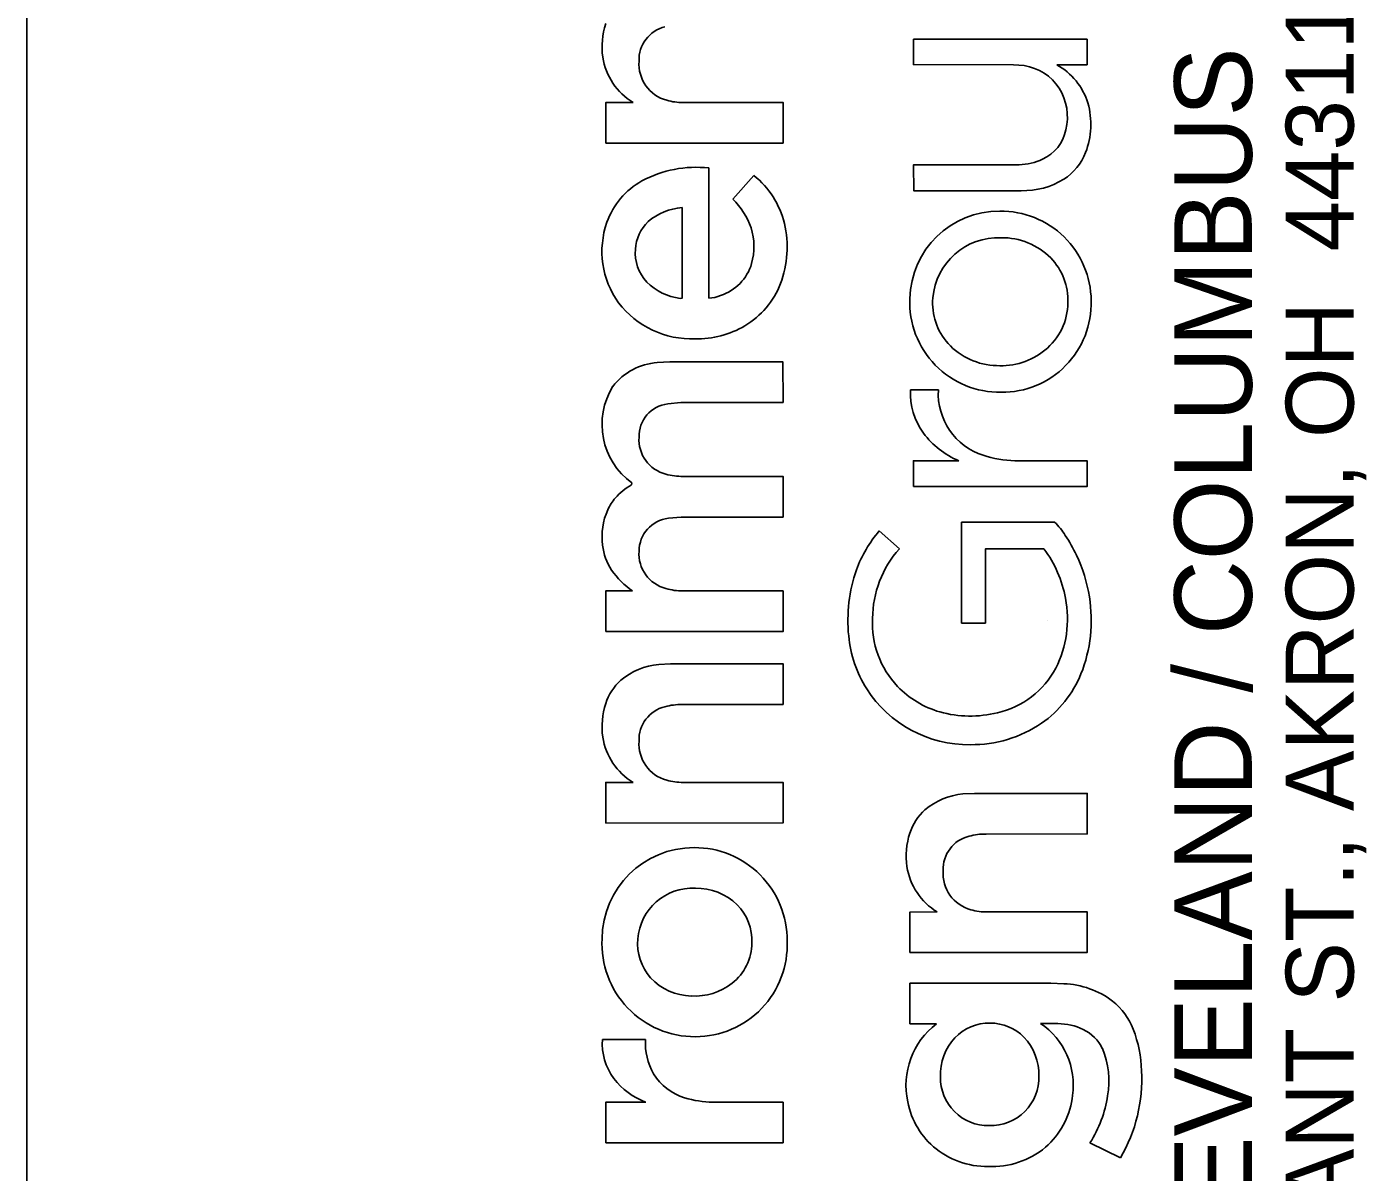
# Model space of a CAD drawing. Extents: x -7 to 3400, y -220 to 22.
# Drawn here: x 32 to 32.984, y 3.594 to 4.436 of the extents above; entities that cross this region are included whole.
import ezdxf

# ---------------------------------------------------------------- set-up
doc = ezdxf.new("R2010")
doc.units = 0
doc.layers.add('SH_Border', color=7, linetype='Continuous')
doc.layers.add('SH_Data', color=7, linetype='Continuous')

msp = doc.modelspace()

# ---------------------------------------------------------------- linework, layer by layer
at = {"layer": 'SH_Border'}
msp.add_line((32, 0.5), (32, 21.5), dxfattribs=at)
at = {"layer": 'SH_Data'}
for p, q in [((32.65152, 4.40801), (32.65153, 4.42672)), ((32.65153, 4.42672), (32.7791, 4.42664)), ((32.7791, 4.42664), (32.77908, 4.40796)), ((32.7249, 4.40796), (32.65152, 4.40801)), ((32.7328, 4.40727), (32.7249, 4.40796)), ((32.77908, 4.40796), (32.75689, 4.40796)), ((32.42542, 4.38016), (32.44552, 4.38021)), ((32.42542, 4.35035), (32.42542, 4.38016)), ((32.48222, 4.38021), (32.55569, 4.38021)), ((32.55569, 4.38021), (32.55571, 4.35045)), ((32.55571, 4.35045), (32.42542, 4.35035)), ((32.50108, 4.33209), (32.50118, 4.23657)), ((32.65154, 4.33443), (32.72905, 4.3345)), ((32.65165, 4.31543), (32.65154, 4.33443)), ((32.51882, 4.30927), (32.53422, 4.32662)), ((32.73073, 4.31543), (32.65165, 4.31543)), ((32.48144, 4.23644), (32.48144, 4.30296)), ((32.48016, 4.23628), (32.48144, 4.23644)), ((32.46329, 4.18915), (32.47259, 4.18968)), ((32.47259, 4.18968), (32.55557, 4.18968)), ((32.55557, 4.18968), (32.55571, 4.15982)), ((32.64932, 4.16907), (32.66978, 4.16907)), ((32.48058, 4.15981), (32.47102, 4.15881)), ((32.55571, 4.15982), (32.48058, 4.15981)), ((32.65152, 4.11699), (32.68476, 4.117)), ((32.65152, 4.098), (32.65152, 4.11699)), ((32.72605, 4.11703), (32.7791, 4.11696)), ((32.7791, 4.11696), (32.77903, 4.098)), ((32.48218, 4.10553), (32.55571, 4.10548)), ((32.55571, 4.10548), (32.55571, 4.07568)), ((32.44443, 4.09922), (32.44455, 4.10072)), ((32.77903, 4.098), (32.65152, 4.098)), ((32.4809, 4.07567), (32.47143, 4.07474)), ((32.55571, 4.07568), (32.4809, 4.07567)), ((32.62636, 4.06548), (32.64114, 4.05241)), ((32.6868, 4.07185), (32.75516, 4.07192)), ((32.6868, 3.99778), (32.6868, 4.07185)), ((32.70448, 4.05241), (32.70432, 3.99775)), ((32.74737, 4.05227), (32.70448, 4.05241)), ((32.42542, 3.99152), (32.42545, 4.02138)), ((32.42545, 4.02138), (32.44515, 4.02138)), ((32.48206, 4.02138), (32.55571, 4.02136)), ((32.55571, 4.02136), (32.55571, 3.99156)), ((32.70432, 3.99775), (32.6868, 3.99778)), ((32.75, 4), (32.75, 4)), ((32.55571, 3.99156), (32.42542, 3.99152)), ((32.46439, 3.96736), (32.47289, 3.96783)), ((32.47289, 3.96783), (32.55571, 3.96783)), ((32.55571, 3.96783), (32.55571, 3.93804)), ((32.55571, 3.93804), (32.4814, 3.93796)), ((32.42542, 3.88066), (32.44552, 3.88071)), ((32.42542, 3.85086), (32.42542, 3.88066)), ((32.48222, 3.88071), (32.55569, 3.88071)), ((32.55569, 3.88071), (32.55571, 3.85096)), ((32.68784, 3.8722), (32.69634, 3.87266)), ((32.69634, 3.87266), (32.77916, 3.87266)), ((32.77916, 3.87266), (32.77917, 3.84287)), ((32.55571, 3.85096), (32.42542, 3.85086)), ((32.77917, 3.84287), (32.70485, 3.8428)), ((32.64888, 3.7855), (32.66897, 3.78555)), ((32.64888, 3.75569), (32.64888, 3.7855)), ((32.70568, 3.78555), (32.77915, 3.78555)), ((32.77915, 3.78555), (32.77917, 3.75579)), ((32.77917, 3.75579), (32.64888, 3.75569)), ((32.6489, 3.70336), (32.64889, 3.73322)), ((32.64889, 3.73322), (32.75236, 3.73322)), ((32.75236, 3.73322), (32.76191, 3.73285)), ((32.66836, 3.70336), (32.6489, 3.70336)), ((32.75763, 3.70356), (32.74487, 3.70361)), ((32.42299, 3.69193), (32.45454, 3.69193)), ((32.42542, 3.64577), (32.45473, 3.64579)), ((32.42542, 3.61593), (32.42542, 3.64577)), ((32.50413, 3.64581), (32.55571, 3.64573)), ((32.55571, 3.64573), (32.55565, 3.61593)), ((32.55565, 3.61593), (32.42542, 3.61593)), ((32.8036, 3.60491), (32.7812, 3.61598))]:
    msp.add_line(p, q, dxfattribs=at)
for points in [[(32.7328, 4.40727), (32.7249, 4.40796), (32.65152, 4.40801), (32.65153, 4.42672), (32.7791, 4.42664), (32.77908, 4.40796), (32.75689, 4.40796)], [(32.42542, 4.35035), (32.42542, 4.38016), (32.44552, 4.38021)], [(32.48222, 4.38021), (32.55569, 4.38021), (32.55571, 4.35045), (32.42542, 4.35035)], [(32.50108, 4.33209), (32.50118, 4.23657)], [(32.73073, 4.31543), (32.65165, 4.31543), (32.65154, 4.33443), (32.72905, 4.3345)], [(32.51882, 4.30927), (32.53422, 4.32662)], [(32.48016, 4.23628), (32.48144, 4.23644), (32.48144, 4.30296)], [(32.46329, 4.18915), (32.47259, 4.18968), (32.55557, 4.18968), (32.55571, 4.15982), (32.48058, 4.15981), (32.47102, 4.15881)], [(32.64932, 4.16907), (32.66978, 4.16907)], [(32.72605, 4.11703), (32.7791, 4.11696), (32.77903, 4.098), (32.65152, 4.098)], [(32.65152, 4.098), (32.65152, 4.11699), (32.68476, 4.117)], [(32.48218, 4.10553), (32.55571, 4.10548), (32.55571, 4.07568), (32.4809, 4.07567), (32.47143, 4.07474)], [(32.44443, 4.09922), (32.44455, 4.10072)], [(32.62636, 4.06548), (32.64114, 4.05241)], [(32.74737, 4.05227), (32.70448, 4.05241), (32.70432, 3.99775), (32.6868, 3.99778), (32.6868, 4.07185), (32.75516, 4.07192)], [(32.42542, 3.99152), (32.42545, 4.02138), (32.44515, 4.02138)], [(32.48206, 4.02138), (32.55571, 4.02136), (32.55571, 3.99156), (32.42542, 3.99152)], [(32.46439, 3.96736), (32.47289, 3.96783), (32.55571, 3.96783), (32.55571, 3.93804), (32.4814, 3.93796)], [(32.42542, 3.85086), (32.42542, 3.88066), (32.44552, 3.88071)], [(32.48222, 3.88071), (32.55569, 3.88071), (32.55571, 3.85096), (32.42542, 3.85086)], [(32.68784, 3.8722), (32.69634, 3.87266), (32.77916, 3.87266), (32.77917, 3.84287), (32.70485, 3.8428)], [(32.64888, 3.75569), (32.64888, 3.7855), (32.66897, 3.78555)], [(32.70568, 3.78555), (32.77915, 3.78555), (32.77917, 3.75579), (32.64888, 3.75569)], [(32.66836, 3.70336), (32.6489, 3.70336), (32.64889, 3.73322), (32.75236, 3.73322), (32.76191, 3.73285)], [(32.75763, 3.70356), (32.74487, 3.70361)], [(32.42299, 3.69193), (32.45454, 3.69193)], [(32.50413, 3.64581), (32.55571, 3.64573), (32.55565, 3.61593), (32.42542, 3.61593)], [(32.42542, 3.61593), (32.42542, 3.64577), (32.45473, 3.64579)], [(32.8036, 3.60491), (32.7812, 3.61598)]]:
    msp.add_lwpolyline(points, dxfattribs=at)
for centre, radius, start, end in [((32.47872, 4.42108), 0.05602, 162.27398, 187.79173), ((32.47872, 4.42108), 0.05602, 162.27398, 187.79173), ((32.47482, 4.41155), 0.02498, 103.68683, 182.21395), ((32.47482, 4.41155), 0.02498, 103.68683, 182.21395), ((32.47027, 4.4209), 0.04763, 188.96462, 238.69865), ((32.47027, 4.4209), 0.04763, 188.96462, 238.69865), ((32.47735, 4.40846), 0.02757, 175.58441, 255.13816), ((32.47735, 4.40846), 0.02757, 175.58441, 255.13816), ((32.72711, 4.36998), 0.03772, 33.50082, 81.32954), ((32.72711, 4.36998), 0.03772, 33.50082, 81.32954), ((32.73239, 4.36485), 0.04959, 17.62209, 60.38974), ((32.73239, 4.36485), 0.04959, 17.62209, 60.38974), ((32.72414, 4.3695), 0.04048, 346.56179, 31.75389), ((32.72414, 4.3695), 0.04048, 346.56179, 31.75389), ((32.48183, 4.42235), 0.04215, 254.08913, 270.52838), ((32.48183, 4.42235), 0.04215, 254.08913, 270.52838), ((32.72343, 4.36415), 0.05838, 339.16197, 15.61485), ((32.72343, 4.36415), 0.05838, 339.16197, 15.61485), ((32.73371, 4.36616), 0.03042, 294.63214, 348.48625), ((32.73371, 4.36616), 0.03042, 294.63214, 348.48625), ((32.739, 4.35901), 0.04201, 303.10391, 338.15613), ((32.739, 4.35901), 0.04201, 303.10391, 338.15613), ((32.49176, 4.24874), 0.08387, 83.62118, 118.28448), ((32.49176, 4.24874), 0.08387, 83.62118, 118.28448), ((32.72747, 4.38081), 0.04633, 271.95199, 294.08943), ((32.72747, 4.38081), 0.04633, 271.95199, 294.08943), ((32.47894, 4.27368), 0.05583, 118.82935, 160.62242), ((32.47894, 4.27368), 0.05583, 118.82935, 160.62242), ((32.49399, 4.2763), 0.06443, 13.53275, 51.36266), ((32.49399, 4.2763), 0.06443, 13.53275, 51.36266), ((32.7321, 4.37256), 0.05715, 268.62699, 301.47779), ((32.7321, 4.37256), 0.05715, 268.62699, 301.47779), ((32.4844, 4.26071), 0.04236, 94.01311, 130.88062), ((32.4844, 4.26071), 0.04236, 94.01311, 130.88062), ((32.48033, 4.27018), 0.05485, 19.0387, 45.44322), ((32.48033, 4.27018), 0.05485, 19.0387, 45.44322), ((32.48697, 4.27074), 0.06438, 160.52138, 215.78155), ((32.48697, 4.27074), 0.06438, 160.52138, 215.78155), ((32.47703, 4.2709), 0.02985, 132.98553, 177.1802), ((32.47703, 4.2709), 0.02985, 132.98553, 177.1802), ((32.48289, 4.27384), 0.0758, 339.35431, 13.37708), ((32.48289, 4.27384), 0.0758, 339.35431, 13.37708), ((32.71435, 4.23484), 0.06552, 89.48213, 178.77752), ((32.71435, 4.23484), 0.06552, 89.48213, 178.77752), ((32.71582, 4.23414), 0.06623, 0.42265, 90.7613), ((32.71582, 4.23414), 0.06623, 0.42265, 90.7613), ((32.48724, 4.27433), 0.04701, 344.60723, 17.00675), ((32.48724, 4.27433), 0.04701, 344.60723, 17.00675), ((32.47824, 4.26966), 0.03114, 175.00138, 223.2876), ((32.47824, 4.26966), 0.03114, 175.00138, 223.2876), ((32.71397, 4.23244), 0.04846, 87.68827, 175.01696), ((32.71397, 4.23244), 0.04846, 87.68827, 175.01696), ((32.71659, 4.23036), 0.05052, 44.91202, 90.75914), ((32.71659, 4.23036), 0.05052, 44.91202, 90.75914), ((32.49895, 4.27177), 0.03504, 288.01084, 343.55364), ((32.49895, 4.27177), 0.03504, 288.01084, 343.55364), ((32.71955, 4.23452), 0.04549, 358.32279, 43.83486), ((32.71955, 4.23452), 0.04549, 358.32279, 43.83486), ((32.48546, 4.27826), 0.04232, 225.06454, 262.79701), ((32.48546, 4.27826), 0.04232, 225.06454, 262.79701), ((32.49548, 4.26982), 0.0626, 300.94393, 338.73223), ((32.49548, 4.26982), 0.0626, 300.94393, 338.73223), ((32.48908, 4.27516), 0.06872, 217.74341, 271.65606), ((32.48908, 4.27516), 0.06872, 217.74341, 271.65606), ((32.50129, 4.25678), 0.02021, 269.70042, 294.87295), ((32.50129, 4.25678), 0.02021, 269.70042, 294.87295), ((32.71483, 4.2334), 0.06606, 177.53728, 270.94524), ((32.71483, 4.2334), 0.06606, 177.53728, 270.94524), ((32.71085, 4.23311), 0.0453, 175.51467, 221.42047), ((32.71085, 4.23311), 0.0453, 175.51467, 221.42047), ((32.71671, 4.23271), 0.06536, 269.30834, 1.67905), ((32.71671, 4.23271), 0.06536, 269.30834, 1.67905), ((32.71931, 4.23374), 0.04572, 308.90382, 359.30947), ((32.71931, 4.23374), 0.04572, 308.90382, 359.30947), ((32.49204, 4.27702), 0.07055, 269.20529, 300.33566), ((32.49204, 4.27702), 0.07055, 269.20529, 300.33566), ((32.71399, 4.23734), 0.05046, 222.66255, 268.37331), ((32.71399, 4.23734), 0.05046, 222.66255, 268.37331), ((32.71567, 4.23859), 0.05178, 266.55312, 308.67253), ((32.71567, 4.23859), 0.05178, 266.55312, 308.67253), ((32.46638, 4.14404), 0.04521, 93.91118, 142.30723), ((32.46638, 4.14404), 0.04521, 93.91118, 142.30723), ((32.47585, 4.14373), 0.05319, 148.28793, 233.9556), ((32.47585, 4.14373), 0.05319, 148.28793, 233.9556), ((32.69878, 4.16662), 0.04952, 177.16211, 216.28024), ((32.69878, 4.16662), 0.04952, 177.16211, 216.28024), ((32.71735, 4.16638), 0.04764, 176.76988, 252.15044), ((32.71735, 4.16638), 0.04764, 176.76988, 252.15044), ((32.47384, 4.13499), 0.02399, 96.75763, 181.6251), ((32.47384, 4.13499), 0.02399, 96.75763, 181.6251), ((32.47577, 4.13241), 0.02597, 175.81573, 256.16716), ((32.47577, 4.13241), 0.02597, 175.81573, 256.16716), ((32.70975, 4.17555), 0.06366, 216.91526, 246.88619), ((32.70975, 4.17555), 0.06366, 216.91526, 246.88619), ((32.7269, 4.19175), 0.07473, 251.13884, 269.34694), ((32.7269, 4.19175), 0.07473, 251.13884, 269.34694), ((32.4817, 4.15053), 0.04501, 254.34629, 270.61033), ((32.4817, 4.15053), 0.04501, 254.34629, 270.61033), ((32.4638, 4.06267), 0.04137, 117.91625, 139.24296), ((32.4638, 4.06267), 0.04137, 117.91625, 139.24296), ((32.46194, 4.06452), 0.03875, 139.52447, 154.84698), ((32.46194, 4.06452), 0.03875, 139.52447, 154.84698), ((32.47144, 4.0612), 0.04877, 156.06382, 187.3493), ((32.47144, 4.0612), 0.04877, 156.06382, 187.3493), ((32.47421, 4.05056), 0.02434, 96.5532, 179.94902), ((32.47421, 4.05056), 0.02434, 96.5532, 179.94902), ((32.70163, 4.00187), 0.09855, 139.79476, 159.13696), ((32.70163, 4.00187), 0.09855, 139.79476, 159.13696), ((32.72498, 4.03937), 0.04438, 30.98913, 47.16099), ((32.72498, 4.03937), 0.04438, 30.98913, 47.16099), ((32.46461, 4.05974), 0.04181, 186.5579, 213.38846), ((32.46461, 4.05974), 0.04181, 186.5579, 213.38846), ((32.67091, 4.00018), 0.11106, 25.30315, 33.96179), ((32.67091, 4.00018), 0.11106, 25.30315, 33.96179), ((32.47608, 4.04863), 0.02628, 175.722, 255.78627), ((32.47608, 4.04863), 0.02628, 175.722, 255.78627), ((32.69899, 4.00079), 0.07753, 138.25804, 179.70064), ((32.69899, 4.00079), 0.07753, 138.25804, 179.70064), ((32.67889, 4.00099), 0.08556, 10.07509, 36.83189), ((32.67889, 4.00099), 0.08556, 10.07509, 36.83189), ((32.6704, 3.99987), 0.11166, 8.80339, 25.33484), ((32.6704, 3.99987), 0.11166, 8.80339, 25.33484), ((32.47886, 4.07078), 0.0598, 214.70433, 235.68724), ((32.47886, 4.07078), 0.0598, 214.70433, 235.68724), ((32.7187, 3.99968), 0.11536, 161.14379, 185.62812), ((32.7187, 3.99968), 0.11536, 161.14379, 185.62812), ((32.48195, 4.06518), 0.0438, 253.66719, 270.14979), ((32.48195, 4.06518), 0.0438, 253.66719, 270.14979), ((32.68425, 4.00057), 0.08036, 333.46689, 11.03668), ((32.68425, 4.00057), 0.08036, 333.46689, 11.03668), ((32.67564, 3.99977), 0.10649, 338.28866, 9.28548), ((32.67564, 3.99977), 0.10649, 338.28866, 9.28548), ((32.68811, 3.99732), 0.06676, 176.66577, 223.6912), ((32.68811, 3.99732), 0.06676, 176.66577, 223.6912), ((32.69336, 3.99699), 0.08987, 185.50773, 212.01294), ((32.69336, 3.99699), 0.08987, 185.50773, 212.01294), ((32.46871, 3.91767), 0.04988, 94.97056, 130.22484), ((32.46871, 3.91767), 0.04988, 94.97056, 130.22484), ((32.69868, 3.99547), 0.0652, 282.88151, 331.81475), ((32.69868, 3.99547), 0.0652, 282.88151, 331.81475), ((32.69835, 3.99168), 0.08241, 305.03061, 337.67573), ((32.69835, 3.99168), 0.08241, 305.03061, 337.67573), ((32.46348, 3.92602), 0.04016, 132.22383, 161.68229), ((32.46348, 3.92602), 0.04016, 132.22383, 161.68229), ((32.69211, 3.99748), 0.08908, 212.70222, 270.71399), ((32.69211, 3.99748), 0.08908, 212.70222, 270.71399), ((32.69045, 4.00011), 0.07039, 224.02147, 253.88), ((32.69045, 4.00011), 0.07039, 224.02147, 253.88), ((32.47872, 3.92158), 0.05602, 162.27398, 187.79173), ((32.47872, 3.92158), 0.05602, 162.27398, 187.79173), ((32.48108, 3.89196), 0.04601, 89.60515, 105.33026), ((32.48108, 3.89196), 0.04601, 89.60515, 105.33026), ((32.47482, 3.91206), 0.02498, 103.68683, 182.21395), ((32.47482, 3.91206), 0.02498, 103.68683, 182.21395), ((32.69318, 4.01254), 0.08309, 254.45353, 283.9512), ((32.69318, 4.01254), 0.08309, 254.45353, 283.9512), ((32.69429, 3.99979), 0.09138, 269.3273, 304.19632), ((32.69429, 3.99979), 0.09138, 269.3273, 304.19632), ((32.47027, 3.92141), 0.04763, 188.96462, 238.69865), ((32.47027, 3.92141), 0.04763, 188.96462, 238.69865), ((32.47735, 3.90897), 0.02757, 175.58441, 255.13816), ((32.47735, 3.90897), 0.02757, 175.58441, 255.13816), ((32.48183, 3.92286), 0.04215, 254.08913, 270.52838), ((32.48183, 3.92286), 0.04215, 254.08913, 270.52838), ((32.69216, 3.82251), 0.04988, 94.97056, 130.22484), ((32.69216, 3.82251), 0.04988, 94.97056, 130.22484), ((32.68694, 3.83085), 0.04016, 132.22383, 161.68229), ((32.68694, 3.83085), 0.04016, 132.22383, 161.68229), ((32.70217, 3.82642), 0.05602, 162.27398, 187.79173), ((32.70217, 3.82642), 0.05602, 162.27398, 187.79173), ((32.69828, 3.81689), 0.02498, 103.68683, 182.21395), ((32.69828, 3.81689), 0.02498, 103.68683, 182.21395), ((32.70453, 3.79679), 0.04601, 89.60515, 105.33026), ((32.70453, 3.79679), 0.04601, 89.60515, 105.33026), ((32.49014, 3.76543), 0.0674, 89.84756, 179.64047), ((32.49014, 3.76543), 0.0674, 89.84756, 179.64047), ((32.49057, 3.76474), 0.0681, 359.54009, 90.21138), ((32.49057, 3.76474), 0.0681, 359.54009, 90.21138), ((32.69372, 3.82624), 0.04763, 188.96462, 238.69865), ((32.69372, 3.82624), 0.04763, 188.96462, 238.69865), ((32.7008, 3.81381), 0.02757, 175.58441, 255.13816), ((32.7008, 3.81381), 0.02757, 175.58441, 255.13816), ((32.48923, 3.76263), 0.0404, 87.04809, 175.57259), ((32.48923, 3.76263), 0.0404, 87.04809, 175.57259), ((32.49204, 3.75999), 0.04299, 45.84264, 90.98008), ((32.49204, 3.75999), 0.04299, 45.84264, 90.98008), ((32.49458, 3.76421), 0.03821, 357.88569, 44.15902), ((32.49458, 3.76421), 0.03821, 357.88569, 44.15902), ((32.70529, 3.82769), 0.04215, 254.08913, 270.52838), ((32.70529, 3.82769), 0.04215, 254.08913, 270.52838), ((32.49083, 3.76209), 0.06819, 176.8344, 270.40384), ((32.49083, 3.76209), 0.06819, 176.8344, 270.40384), ((32.48729, 3.7625), 0.03848, 175.15378, 221.14706), ((32.48729, 3.7625), 0.03848, 175.15378, 221.14706), ((32.49123, 3.76139), 0.06749, 270.06243, 2.37759), ((32.49123, 3.76139), 0.06749, 270.06243, 2.37759), ((32.49446, 3.76318), 0.0383, 308.28936, 359.43468), ((32.49446, 3.76318), 0.0383, 308.28936, 359.43468), ((32.48919, 3.76607), 0.04228, 223.09994, 268.80895), ((32.48919, 3.76607), 0.04228, 223.09994, 268.80895), ((32.49096, 3.7679), 0.04418, 266.56515, 308.06078), ((32.49096, 3.7679), 0.04418, 266.56515, 308.06078), ((32.75907, 3.66789), 0.06503, 53.40344, 87.49062), ((32.75907, 3.66789), 0.06503, 53.40344, 87.49062), ((32.76517, 3.68039), 0.05141, 21.60748, 50.5577), ((32.76517, 3.68039), 0.05141, 21.60748, 50.5577), ((32.70292, 3.65813), 0.05692, 127.37482, 192.22468), ((32.70292, 3.65813), 0.05692, 127.37482, 192.22468), ((32.70693, 3.66927), 0.0346, 88.47302, 136.42562), ((32.70693, 3.66927), 0.0346, 88.47302, 136.42562), ((32.70814, 3.66963), 0.03424, 44.27195, 90.47623), ((32.70814, 3.66963), 0.03424, 44.27195, 90.47623), ((32.71421, 3.65829), 0.05472, 352.1125, 55.92295), ((32.71421, 3.65829), 0.05472, 352.1125, 55.92295), ((32.75666, 3.65725), 0.04633, 65.01687, 88.8011), ((32.75666, 3.65725), 0.04633, 65.01687, 88.8011), ((32.46616, 3.68882), 0.04329, 175.87313, 216.34747), ((32.46616, 3.68882), 0.04329, 175.87313, 216.34747), ((32.50087, 3.68948), 0.04639, 176.9688, 209.60636), ((32.50087, 3.68948), 0.04639, 176.9688, 209.60636), ((32.71141, 3.66602), 0.0401, 137.46739, 182.33237), ((32.71141, 3.66602), 0.0401, 137.46739, 182.33237), ((32.70368, 3.666), 0.03996, 358.57141, 43.53765), ((32.70368, 3.666), 0.03996, 358.57141, 43.53765), ((32.7626, 3.67155), 0.03085, 26.26808, 63.80301), ((32.7626, 3.67155), 0.03085, 26.26808, 63.80301), ((32.73069, 3.66714), 0.08835, 1.15143, 21.3627), ((32.73069, 3.66714), 0.08835, 1.15143, 21.3627), ((32.73565, 3.66154), 0.05953, 349.30734, 23.43071), ((32.73565, 3.66154), 0.05953, 349.30734, 23.43071), ((32.47466, 3.69716), 0.05511, 218.09809, 248.7907), ((32.47466, 3.69716), 0.05511, 218.09809, 248.7907), ((32.49514, 3.68814), 0.04079, 211.94466, 253.2028), ((32.49514, 3.68814), 0.04079, 211.94466, 253.2028), ((32.70645, 3.6637), 0.03511, 178.88208, 271.08374), ((32.70645, 3.6637), 0.03511, 178.88208, 271.08374), ((32.70818, 3.66404), 0.03546, 268.27882, 1.55016), ((32.70818, 3.66404), 0.03546, 268.27882, 1.55016), ((32.70538, 3.66244), 0.11383, 329.6388, 3.25998), ((32.70538, 3.66244), 0.11383, 329.6388, 3.25998), ((32.50465, 3.7165), 0.07069, 252.46555, 269.57296), ((32.50465, 3.7165), 0.07069, 252.46555, 269.57296), ((32.70463, 3.65696), 0.05837, 190.75182, 231.28919), ((32.70463, 3.65696), 0.05837, 190.75182, 231.28919), ((32.70988, 3.65708), 0.05887, 313.74196, 353.8554), ((32.70988, 3.65708), 0.05887, 313.74196, 353.8554), ((32.70738, 3.66334), 0.08771, 327.31495, 351.57478), ((32.70738, 3.66334), 0.08771, 327.31495, 351.57478), ((32.70954, 3.65901), 0.06051, 269.6361, 312.70877), ((32.70954, 3.65901), 0.06051, 269.6361, 312.70877), ((32.70632, 3.66112), 0.06269, 232.46061, 272.59022), ((32.70632, 3.66112), 0.06269, 232.46061, 272.59022)]:
    msp.add_arc(centre, radius, start, end, dxfattribs=at)

# ---------------------------------------------------------------- texts
for s, height, p in [('450 GRANT ST., AKRON, OH  44311', 0.0498462, (32.97489, 3.33738)), ('AKRON / CLEVELAND / COLUMBUS', 0.056969, (32.90012, 3.138))]:
    msp.add_text(s, height=height, rotation=90, dxfattribs=at).set_placement(p)

doc.saveas('drawing.dxf')
